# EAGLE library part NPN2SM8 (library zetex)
Dual NPN TRANSISTOR
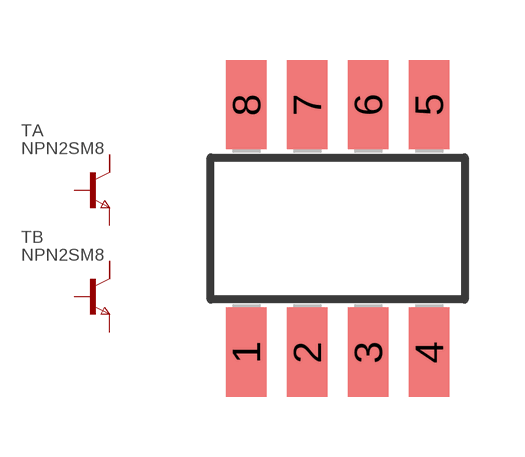
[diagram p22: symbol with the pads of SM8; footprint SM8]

Designator prefix T; gates A=NPN2C B=NPN2C

## NPN2SM8 (OC_FARNELL: unknown; OC_NEWARK: unknown)  [SM8]
1  B:E  pas
2  B:B  pas
3  A:E  pas
4  A:B  pas
5  A:C1  pas
6  A:C2  pas
7  B:C1  pas
8  B:C2  pas

## Footprint SM8 (pad centres in mm)
SM8 Package
smd 1.016 x 2.235: 1 -2.286,-3.099; 2 -0.762,-3.099; 3 0.762,-3.099; 4 2.286,-3.099; 5 2.286,3.099; 6 0.762,3.099; 7 -0.762,3.099; 8 -2.286,3.099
